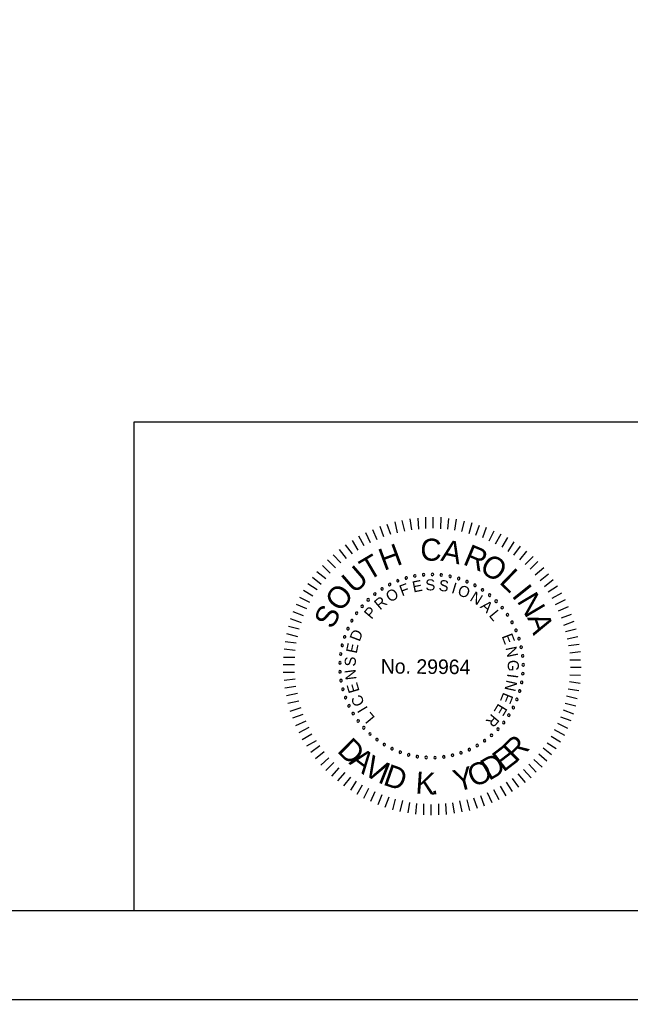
# Model space of a CAD drawing. Extents: x -133.1 to -97, y -1.7 to 20.3.
# Drawn here: x -111.15 to -107.71, y -1.69 to 3.82 of the extents above; entities that cross this region are included whole.
import ezdxf

# ---------------------------------------------------------------- set-up
doc = ezdxf.new("R2010")
doc.units = 0
for name, color, linetype in [('BR_BORDER LINES', 7, 'Continuous'), ('BR_TEXT', 7, 'Continuous'), ('Level 31', 7, 'Continuous')]:
    doc.layers.add(name, color=color, linetype=linetype)

msp = doc.modelspace()

# ---------------------------------------------------------------- linework, layer by layer
at = {"layer": 'BR_BORDER LINES'}
for p, q in [((-110.5071, 1.5591), (-105.1419, 1.5591)), ((-110.5071, -1.191), (-110.5071, 1.5591)), ((-131.3076, -1.191), (-97.6416, -1.191))]:
    msp.add_line(p, q, dxfattribs=at)
at = {"layer": 'BR_TEXT'}
for p, q in [((-109.0262, 0.9348), (-109.0394, 0.9958)), ((-108.9849, 0.9447), (-108.999, 1.0041)), ((-108.9454, 0.9521), (-108.9543, 1.0131)), ((-108.9059, 0.9561), (-108.9097, 1.017)), ((-108.8664, 0.9584), (-108.8658, 1.0227)), ((-108.8243, 0.9606), (-108.8238, 1.0224)), ((-108.7823, 0.9577), (-108.78, 1.022)), ((-108.742, 0.9548), (-108.7372, 1.0156)), ((-108.7034, 0.9501), (-108.6926, 1.011)), ((-108.6631, 0.9421), (-108.6489, 1.0012)), ((-109.1406, 0.8954), (-109.1642, 0.9514)), ((-109.1019, 0.9122), (-109.1229, 0.9708)), ((-109.0623, 0.9248), (-109.0842, 0.9824)), ((-108.622, 0.9314), (-108.606, 0.9922)), ((-108.5852, 0.9208), (-108.5633, 0.9781)), ((-108.5458, 0.9076), (-108.5239, 0.9658)), ((-108.5099, 0.8902), (-108.482, 0.9457)), ((-109.2475, 0.8371), (-109.278, 0.8914)), ((-109.2122, 0.8608), (-109.2426, 0.9151)), ((-109.1777, 0.8785), (-109.2039, 0.9345)), ((-108.474, 0.8727), (-108.4427, 0.9282)), ((-108.4364, 0.8544), (-108.4042, 0.9082)), ((-108.4031, 0.8301), (-108.3692, 0.8839)), ((-109.3123, 0.7904), (-109.3522, 0.8405)), ((-109.2786, 0.8159), (-109.3177, 0.8668)), ((-108.3699, 0.8083), (-108.3334, 0.8587)), ((-108.3375, 0.7824), (-108.2968, 0.8318)), ((-109.3745, 0.7386), (-109.4188, 0.7827)), ((-109.3451, 0.7658), (-109.3868, 0.8107)), ((-108.3059, 0.7572), (-108.2627, 0.8014)), ((-108.2779, 0.7295), (-108.2346, 0.7729)), ((-109.4039, 0.7079), (-109.4474, 0.7503)), ((-108.2498, 0.6984), (-108.2022, 0.74)), ((-109.4551, 0.6431), (-109.5046, 0.683)), ((-109.4291, 0.6763), (-109.4786, 0.7154)), ((-108.2226, 0.6664), (-108.1759, 0.7046)), ((-108.1988, 0.6327), (-108.1496, 0.6718)), ((-109.5012, 0.5774), (-109.5549, 0.6096)), ((-109.4768, 0.6141), (-109.5306, 0.6472)), ((-108.1768, 0.6034), (-108.1242, 0.6355)), ((-109.5186, 0.5432), (-109.575, 0.5711)), ((-108.1548, 0.5663), (-108.1013, 0.5976)), ((-108.137, 0.5318), (-108.0793, 0.5588)), ((-109.5361, 0.5065), (-109.5933, 0.5318)), ((-108.1193, 0.4948), (-108.0624, 0.5192)), ((-109.5659, 0.4278), (-109.6275, 0.4506)), ((-109.5536, 0.468), (-109.6117, 0.4899)), ((-108.1025, 0.456), (-108.0456, 0.477)), ((-109.5782, 0.3918), (-109.639, 0.4069)), ((-108.0891, 0.4156), (-108.0314, 0.4374)), ((-108.079, 0.3794), (-108.0189, 0.3935)), ((-109.5854, 0.3498), (-109.6479, 0.3658)), ((-108.0708, 0.3373), (-108.0106, 0.3522)), ((-109.6006, 0.2727), (-109.6624, 0.2801)), ((-109.596, 0.3138), (-109.6569, 0.3221)), ((-108.0625, 0.3012), (-108.0033, 0.3084)), ((-109.6035, 0.2333), (-109.6679, 0.2338)), ((-108.056, 0.26), (-107.995, 0.2663)), ((-109.6056, 0.1921), (-109.6682, 0.1926)), ((-108.0546, 0.2205), (-107.9945, 0.22)), ((-108.0524, 0.1793), (-107.9915, 0.1788)), ((-109.6042, 0.1492), (-109.6686, 0.148)), ((-109.602, 0.1105), (-109.6638, 0.1033)), ((-108.0553, 0.1364), (-107.9952, 0.1342)), ((-109.598, 0.0693), (-109.659, 0.0604)), ((-108.0645, 0.0566), (-108.0054, 0.0467)), ((-108.0574, 0.0978), (-107.9965, 0.0896)), ((-109.5881, 0.0297), (-109.6508, 0.0165)), ((-108.0735, 0.0172), (-108.0135, 0.003)), ((-109.5815, -0.0124), (-109.6426, -0.0265)), ((-109.5698, -0.0493), (-109.6318, -0.0703)), ((-108.0824, -0.0248), (-108.0224, -0.0398)), ((-109.5582, -0.0881), (-109.6167, -0.1091)), ((-108.107, -0.1001), (-108.0506, -0.122)), ((-108.093, -0.0615), (-108.0357, -0.0835)), ((-109.5413, -0.1251), (-109.599, -0.1521)), ((-109.5244, -0.1613), (-109.5813, -0.1909)), ((-108.1245, -0.1368), (-108.0681, -0.1647)), ((-109.5076, -0.1984), (-109.5619, -0.2297)), ((-108.1612, -0.2095), (-108.1082, -0.2417)), ((-108.1428, -0.1727), (-108.0856, -0.2032)), ((-109.4838, -0.2355), (-109.5382, -0.2668)), ((-109.4626, -0.2648), (-109.5127, -0.3013)), ((-108.2063, -0.2752), (-108.1577, -0.3125)), ((-108.1838, -0.2462), (-108.1317, -0.2784)), ((-109.4372, -0.2985), (-109.4873, -0.3376)), ((-108.2306, -0.3084), (-108.1846, -0.3483)), ((-109.4125, -0.3321), (-109.4567, -0.373)), ((-109.3836, -0.3582), (-109.4286, -0.4032)), ((-108.2869, -0.3672), (-108.2444, -0.413)), ((-108.2583, -0.3417), (-108.2115, -0.3833)), ((-109.3547, -0.3884), (-109.3971, -0.4344)), ((-109.3222, -0.4144), (-109.363, -0.4613)), ((-109.289, -0.4404), (-109.3289, -0.4882)), ((-108.3474, -0.4225), (-108.3075, -0.47)), ((-108.3155, -0.397), (-108.273, -0.4437)), ((-109.2583, -0.4622), (-109.2896, -0.5142)), ((-109.2233, -0.4847), (-109.2546, -0.5386)), ((-108.4475, -0.4911), (-108.4162, -0.5455)), ((-108.4139, -0.4691), (-108.3808, -0.5217)), ((-108.3802, -0.448), (-108.3446, -0.4963)), ((-109.1891, -0.5048), (-109.2162, -0.5603)), ((-109.1523, -0.5222), (-109.1769, -0.5778)), ((-109.1139, -0.5397), (-109.1358, -0.5962)), ((-108.5578, -0.5443), (-108.5368, -0.6011)), ((-108.5216, -0.5274), (-108.4947, -0.5835)), ((-108.4855, -0.5106), (-108.455, -0.5666)), ((-109.0745, -0.552), (-109.0973, -0.6102)), ((-109.0386, -0.5644), (-109.0528, -0.6235)), ((-108.9974, -0.5716), (-109.0126, -0.6333)), ((-108.9581, -0.5831), (-108.968, -0.6413)), ((-108.9186, -0.5877), (-108.9234, -0.6494)), ((-108.8792, -0.5906), (-108.8797, -0.6524)), ((-108.8372, -0.5935), (-108.8377, -0.6544)), ((-108.7951, -0.5913), (-108.7939, -0.6531)), ((-108.7547, -0.589), (-108.7509, -0.6509)), ((-108.7161, -0.5851), (-108.7062, -0.6435)), ((-108.6756, -0.5742), (-108.6624, -0.6361)), ((-108.6344, -0.5677), (-108.6194, -0.627)), ((-108.5974, -0.556), (-108.5764, -0.6145))]:
    msp.add_line(p, q, dxfattribs=at)
for centre, start, end in [((-109.0235, 0.6646), 21.6807, 201.6807), ((-109.0235, 0.6646), 201.6807, 21.6807), ((-108.9763, 0.6806), 16.1422, 196.1422), ((-108.9763, 0.6806), 196.1422, 16.1422), ((-108.9278, 0.692), 10.6038, 190.6038), ((-108.9278, 0.692), 190.6038, 10.6038), ((-108.8784, 0.6987), 5.0653, 185.0653), ((-108.8784, 0.6987), 185.0653, 5.0653), ((-108.8286, 0.7006), 359.5268, 179.5268), ((-108.8286, 0.7006), 179.5268, 359.5268), ((-108.7789, 0.6977), 173.9884, 353.9884), ((-108.7789, 0.6977), 353.9884, 173.9884), ((-108.7296, 0.69), 168.4499, 348.4499), ((-108.7296, 0.69), 348.4499, 168.4499), ((-108.6814, 0.6776), 162.9114, 342.9114), ((-108.6814, 0.6776), 342.9114, 162.9114), ((-108.6345, 0.6606), 157.373, 337.373), ((-108.6345, 0.6606), 337.373, 157.373), ((-109.1121, 0.6192), 32.7576, 212.7576), ((-109.1121, 0.6192), 212.7576, 32.7576), ((-109.0689, 0.644), 27.2191, 207.2191), ((-109.0689, 0.644), 207.2191, 27.2191), ((-108.5896, 0.6391), 151.8345, 331.8345), ((-108.5896, 0.6391), 331.8345, 151.8345), ((-108.5469, 0.6134), 146.2961, 326.2961), ((-108.5469, 0.6134), 326.2961, 146.2961), ((-109.1903, 0.5577), 43.8345, 223.8345), ((-109.1903, 0.5577), 223.8345, 43.8345), ((-109.1527, 0.5903), 38.2961, 218.2961), ((-109.1527, 0.5903), 218.2961, 38.2961), ((-108.5069, 0.5837), 140.7576, 320.7576), ((-108.5069, 0.5837), 320.7576, 140.7576), ((-108.4699, 0.5503), 135.2191, 315.2191), ((-108.4699, 0.5503), 315.2191, 135.2191), ((-109.2246, 0.5215), 49.373, 229.373), ((-109.2246, 0.5215), 229.373, 49.373), ((-108.4363, 0.5134), 129.6807, 309.6807), ((-108.4363, 0.5134), 309.6807, 129.6807), ((-109.282, 0.4402), 60.4499, 240.4499), ((-109.282, 0.4402), 240.4499, 60.4499), ((-109.2553, 0.4822), 54.9114, 234.9114), ((-109.2553, 0.4822), 234.9114, 54.9114), ((-108.4065, 0.4735), 124.1422, 304.1422), ((-108.4065, 0.4735), 304.1422, 124.1422), ((-109.3045, 0.3957), 65.9884, 245.9884), ((-109.3045, 0.3957), 245.9884, 65.9884), ((-108.3806, 0.4309), 118.6038, 298.6038), ((-108.3806, 0.4309), 298.6038, 118.6038), ((-108.359, 0.3861), 113.0653, 293.0653), ((-108.359, 0.3861), 293.0653, 113.0653), ((-109.3227, 0.3493), 71.5268, 251.5268), ((-109.3227, 0.3493), 251.5268, 71.5268), ((-108.3418, 0.3393), 107.5268, 287.5268), ((-108.3418, 0.3393), 287.5268, 107.5268), ((-109.3363, 0.3014), 77.0653, 257.0653), ((-109.3363, 0.3014), 257.0653, 77.0653), ((-108.3292, 0.2911), 101.9884, 281.9884), ((-108.3292, 0.2911), 281.9884, 101.9884), ((-109.3452, 0.2524), 82.6038, 262.6038), ((-109.3452, 0.2524), 262.6038, 82.6038), ((-108.3213, 0.2419), 96.4499, 276.4499), ((-108.3213, 0.2419), 276.4499, 96.4499), ((-109.3493, 0.2027), 88.1422, 268.1422), ((-109.3493, 0.2027), 268.1422, 88.1422), ((-108.3182, 0.1921), 90.9114, 270.9114), ((-108.3182, 0.1921), 270.9114, 90.9114), ((-109.3486, 0.1529), 93.6807, 273.6807), ((-109.3486, 0.1529), 273.6807, 93.6807), ((-109.3431, 0.1033), 279.2191, 99.2191), ((-108.3199, 0.1423), 85.373, 265.373), ((-108.3199, 0.1423), 265.373, 85.373), ((-109.3431, 0.1033), 99.2191, 279.2191), ((-109.3328, 0.0546), 104.7576, 284.7576), ((-109.3328, 0.0546), 284.7576, 104.7576), ((-108.3265, 0.0929), 79.8345, 259.8345), ((-108.3265, 0.0929), 259.8345, 79.8345), ((-109.3179, 0.007), 110.2961, 290.2961), ((-109.3179, 0.007), 290.2961, 110.2961), ((-108.3536, -0.0028), 68.7576, 248.7576), ((-108.3536, -0.0028), 248.7576, 68.7576), ((-108.3377, 0.0444), 74.2961, 254.2961), ((-108.3377, 0.0444), 254.2961, 74.2961), ((-109.2985, -0.0389), 115.8345, 295.8345), ((-109.2985, -0.0389), 295.8345, 115.8345), ((-108.374, -0.0483), 63.2191, 243.2191), ((-108.374, -0.0483), 243.2191, 63.2191), ((-109.2747, -0.0826), 121.373, 301.373), ((-109.2747, -0.0826), 301.373, 121.373), ((-108.3986, -0.0916), 57.6807, 237.6807), ((-108.3986, -0.0916), 237.6807, 57.6807), ((-109.2468, -0.1239), 126.9114, 306.9114), ((-109.2468, -0.1239), 306.9114, 126.9114), ((-109.2151, -0.1624), 132.4499, 312.4499), ((-109.2151, -0.1624), 312.4499, 132.4499), ((-108.4599, -0.1701), 46.6038, 226.6038), ((-108.4599, -0.1701), 226.6038, 46.6038), ((-108.4273, -0.1323), 52.1422, 232.1422), ((-108.4273, -0.1323), 232.1422, 52.1422), ((-109.1798, -0.1975), 137.9884, 317.9884), ((-109.1798, -0.1975), 317.9884, 137.9884), ((-108.4959, -0.2045), 41.0653, 221.0653), ((-108.4959, -0.2045), 221.0653, 41.0653), ((-109.1413, -0.2291), 143.5268, 323.5268), ((-109.1413, -0.2291), 323.5268, 143.5268), ((-109.0999, -0.2569), 149.0653, 329.0653), ((-109.0999, -0.2569), 329.0653, 149.0653), ((-109.056, -0.2805), 334.6038, 154.6038), ((-108.577, -0.2622), 29.9884, 209.9884), ((-108.577, -0.2622), 209.9884, 29.9884), ((-108.5351, -0.2353), 35.5268, 215.5268), ((-108.5351, -0.2353), 215.5268, 35.5268), ((-109.056, -0.2805), 154.6038, 334.6038), ((-109.01, -0.2997), 160.1422, 340.1422), ((-109.01, -0.2997), 340.1422, 160.1422), ((-108.9624, -0.3145), 165.6807, 345.6807), ((-108.9624, -0.3145), 345.6807, 165.6807), ((-108.9136, -0.3245), 171.2191, 351.2191), ((-108.9136, -0.3245), 351.2191, 171.2191), ((-108.8641, -0.3299), 356.7576, 176.7576), ((-108.8641, -0.3299), 176.7576, 356.7576), ((-108.8142, -0.3304), 2.2961, 182.2961), ((-108.8142, -0.3304), 182.2961, 2.2961), ((-108.7646, -0.3261), 7.8345, 187.8345), ((-108.7646, -0.3261), 187.8345, 7.8345), ((-108.7156, -0.317), 13.373, 193.373), ((-108.7156, -0.317), 193.373, 13.373), ((-108.6677, -0.3032), 18.9114, 198.9114), ((-108.6677, -0.3032), 198.9114, 18.9114), ((-108.6214, -0.2849), 24.4499, 204.4499), ((-108.6214, -0.2849), 204.4499, 24.4499)]:
    msp.add_arc(centre, 0.00701, start, end, dxfattribs=at)
at = {"layer": 'Level 31'}
msp.add_lwpolyline([(-133.1409, -1.691), (-97.141, -1.691), (-97.141, 20.309), (-133.1409, 20.309)], close=True, dxfattribs=at)

# ---------------------------------------------------------------- texts
at = {"layer": 'BR_TEXT'}
for s, height, rotation, p in [('C', 0.1241, 359.5482, (-108.8971, 0.7782)), ('A', 0.1241, 348.1981, (-108.7857, 0.779)), ('H', 0.1241, 20.3637, (-109.1015, 0.7199)), ('R', 0.1241, 337.4344, (-108.6624, 0.7591)), ('T', 0.1241, 30.4992, (-109.1894, 0.6624)), ('O', 0.1239, 326.5869, (-108.5702, 0.7224)), ('U', 0.1241, 40.8022, (-109.2706, 0.5876)), ('L', 0.1241, 315.9488, (-108.4576, 0.6546)), ('E', 0.0622, 11.4103, (-108.9351, 0.5987)), ('S', 0.0622, 2.208, (-108.8672, 0.6097)), ('S', 0.0622, 352.6608, (-108.796, 0.6095)), ('O', 0.1241, 52.0267, (-109.3451, 0.4837)), ('O', 0.0622, 30.8477, (-109.0676, 0.541)), ('F', 0.0622, 20.6127, (-109.0002, 0.577)), ('I', 0.0622, 343.1136, (-108.7257, 0.5975)), ('O', 0.0622, 338.4392, (-108.6923, 0.5873)), ('I', 0.1241, 308.6613, (-108.3862, 0.5803)), ('R', 0.0622, 40.3949, (-109.1237, 0.4971)), ('N', 0.0622, 328.2042, (-108.6227, 0.5559)), ('N', 0.1241, 300.7037, (-108.3556, 0.5509)), ('S', 0.1239, 63.2511, (-109.3905, 0.3881)), ('P', 0.0622, 49.9421, (-109.1718, 0.4445)), ('A', 0.0622, 318.657, (-108.5637, 0.5159)), ('L', 0.0622, 309.4546, (-108.5139, 0.4686)), ('A', 0.1241, 289.4792, (-108.2964, 0.4579)), ('D', 0.0622, 69.0364, (-109.2388, 0.3192)), ('E', 0.0622, 291.049, (-108.44, 0.3533)), ('E', 0.0622, 78.2388, (-109.2553, 0.2526)), ('N', 0.0622, 281.8466, (-108.4179, 0.2882)), ('S', 0.0622, 87.786, (-109.2611, 0.1815)), ('No. 29964', 0.08175, 359.5268, (-109.1199, 0.1431)), ('G', 0.0622, 272.2995, (-108.4061, 0.2179)), ('N', 0.0622, 97.3332, (-109.2549, 0.1105)), ('I', 0.0622, 262.4084, (-108.4065, 0.1441)), ('E', 0.0622, 106.5355, (-109.2379, 0.044)), ('N', 0.0622, 257.7339, (-108.411, 0.1095)), ('C', 0.0622, 116.4266, (-109.208, -0.0235)), ('E', 0.0622, 248.1867, (-108.4291, 0.0406)), ('I', 0.0622, 121.1011, (-109.1899, -0.0534)), ('E', 0.0622, 238.9844, (-108.457, -0.0222)), ('L', 0.0622, 129.9595, (-109.1493, -0.1056)), ('R', 0.0622, 229.782, (-108.4947, -0.0797)), ('D', 0.1236, 315.4053, (-109.3698, -0.2962)), ('R', 0.1236, 44.5947, (-108.3589, -0.3617)), ('E', 0.1236, 37.5339, (-108.4295, -0.4156)), ('A', 0.1236, 322.8377, (-109.3032, -0.3618)), ('V', 0.1236, 330.5179, (-109.226, -0.42)), ('D', 0.1236, 30.1015, (-108.5104, -0.4626)), ('I', 0.1236, 338.1981, (-109.1418, -0.4674)), ('D', 0.1236, 340.7995, (-109.1119, -0.4808)), ('Y', 0.1236, 14.8649, (-108.6915, -0.5241)), ('O', 0.1236, 22.4212, (-108.5997, -0.4996)), ('K', 0.1236, 356.098, (-108.9267, -0.5314)), ('.', 0.1236, 3.1588, (-108.838, -0.5377))]:
    msp.add_text(s, height=height, rotation=rotation, dxfattribs=at).set_placement(p)

doc.saveas('drawing.dxf')
